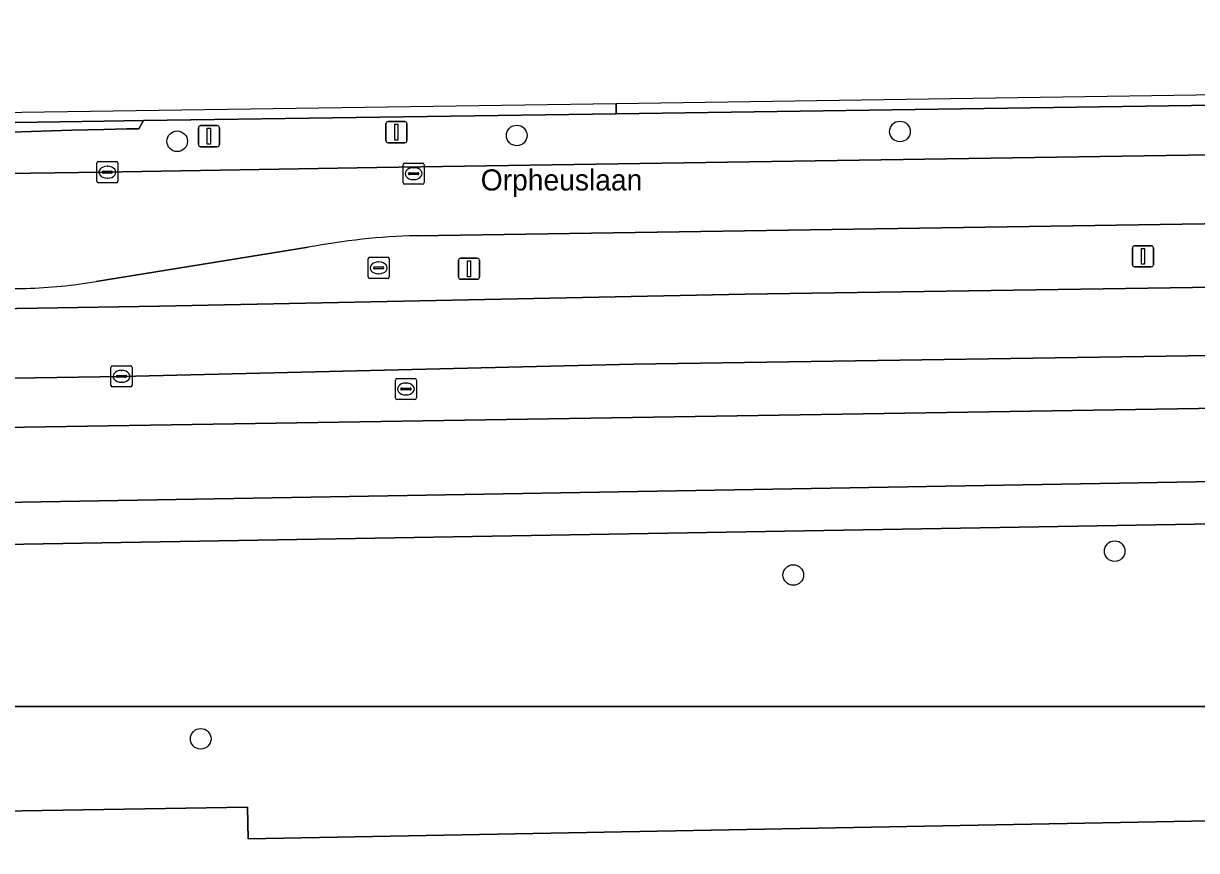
# Model space of a CAD drawing. Extents: x 161758 to 162722, y 384793 to 385405.
# Drawn here: x 162200.5 to 162256.1, y 385350.4 to 385389.6 of the extents above; entities that cross this region are included whole.
import ezdxf

# ---------------------------------------------------------------- set-up
doc = ezdxf.new("R2010")
doc.units = 0
for name, color, linetype in [('IMGEO_Berm_groen', 7, 'Continuous'), ('IMGEO_Boom', 7, 'Continuous'), ('IMGEO_Fietspad_gesloten', 7, 'Continuous'), ('IMGEO_Greppel_droge_sloot', 7, 'Continuous'), ('IMGEO_Groenvoorziening', 7, 'Continuous'), ('IMGEO_Hek', 7, 'Continuous'), ('IMGEO_Kolk', 7, 'Continuous'), ('IMGEO_Lichtmast', 7, 'Continuous'), ('IMGEO_Openbare_ruimte_label', 7, 'Continuous'), ('IMGEO_Rijbaan_lokaal_gesloten', 7, 'Continuous'), ('IMGEO_Rijbaan_lokaal_open', 7, 'Continuous'), ('IMGEO_Rioolput', 7, 'Continuous'), ('IMGEO_Verkeersbordpaal', 7, 'Continuous'), ('IMGEO_Voetpad_open', 7, 'Continuous')]:
    doc.layers.add(name, color=color, linetype=linetype)

msp = doc.modelspace()

# ---------------------------------------------------------------- linework, layer by layer
at = {"layer": 'IMGEO_Berm_groen'}
for points in [[(162448.206, 385387.415), (162445.243, 385388.157), (162443.232, 385388.399), (162423.379, 385388.189), (162414.607, 385388.138), (162283.634, 385386.126), (162263.488, 385385.822), (162228.595, 385385.317), (162206.198, 385385.003), (162205.968, 385384.605), (162205.396, 385384.605), (162204.311, 385384.582), (162202.798, 385384.551), (162199.912, 385384.449), (162195.254, 385384.428), (162192.04, 385384.388), (162191.677, 385384.787), (162189.594, 385384.756), (162154.105, 385384.195)], [(162153.641, 385381.789), (162191.763, 385382.388), (162204.253, 385382.553), (162217.246, 385382.783), (162312.827, 385384.23), (162410.768, 385385.625), (162434.016, 385385.96), (162448.099, 385386.389)], [(162403.86, 385374.889), (162402.9, 385374.878), (162402.901, 385376.061), (162229.409, 385373.457), (162205.151, 385372.883), (162158.028, 385372.147), (162153.757, 385371.662), (162153.722, 385371.658)], [(162192.137, 385370.17), (162199.552, 385370.454), (162335.66, 385372.624)], [(162334.969, 385369.062), (162262.45, 385367.992), (162199.528, 385366.908), (162192.263, 385366.577)], [(162154.507, 385360.425), (162151.789, 385360.357), (162150.992, 385358.051), (162159.583, 385359.12), (162165.376, 385360.213), (162170.222, 385360.838), (162177.201, 385361.095), (162182.531, 385363.894), (162186.248, 385363.968), (162192.408, 385364.581), (162199.591, 385364.909), (162262.482, 385365.992), (162334.984, 385367.062), (162355.205, 385367.058), (162375.991, 385366.088), (162383.594, 385365.585), (162400.648, 385364.015), (162400.746, 385366.014), (162383.752, 385367.579), (162376.104, 385368.085)]]:
    msp.add_lwpolyline(points, dxfattribs=at)
at = {"layer": 'IMGEO_Boom'}
for centre in [(162207.789, 385384.021), (162223.88, 385384.298), (162242.036, 385384.488), (162252.213, 385364.601), (162236.985, 385363.469), (162208.902, 385355.708)]:
    msp.add_circle(centre, 0.489, dxfattribs=at)
at = {"layer": 'IMGEO_Fietspad_gesloten'}
for points in [[(162335.66, 385372.624), (162199.552, 385370.454), (162192.137, 385370.17)], [(162192.263, 385366.577), (162199.528, 385366.908), (162262.45, 385367.992), (162334.969, 385369.062)]]:
    msp.add_lwpolyline(points, dxfattribs=at)
at = {"layer": 'IMGEO_Greppel_droge_sloot'}
for points in [[(162153.729, 385375.343), (162153.782, 385375.344), (162206.944, 385376.203), (162234.699, 385376.782), (162403.236, 385379.286), (162426.371, 385379.655), (162426.501, 385379.723), (162432.165, 385379.785), (162432.018, 385382.777)], [(162432.018, 385382.777), (162411.112, 385382.403), (162393.993, 385382.082), (162339.389, 385381.368), (162219.127, 385379.546)], [(162214.002, 385378.999), (162203.942, 385377.381)], [(162200.627, 385377.052), (162153.77, 385376.293)]]:
    msp.add_lwpolyline(points, dxfattribs=at)
for centre, radius, start, end in [((162219.818, 385348.786), 30.768, 91.2877, 100.8968), ((162199.995, 385400.289), 23.245, 271.5588, 279.7768)]:
    msp.add_arc(centre, radius, start, end, dxfattribs=at)
at = {"layer": 'IMGEO_Groenvoorziening'}
msp.add_lwpolyline([(162400.648, 385364.015), (162383.594, 385365.585), (162375.991, 385366.088), (162355.205, 385367.058), (162334.984, 385367.062), (162262.482, 385365.992), (162199.591, 385364.909), (162192.408, 385364.581), (162186.248, 385363.968), (162185.022, 385359.083), (162186.31, 385357.233), (162276.605, 385357.233), (162354.415, 385358.921), (162400.44, 385359.797)], close=True, dxfattribs=at)
for points in [[(162147.884, 385351.44), (162211.124, 385352.462), (162211.155, 385350.962), (162286.233, 385352.376), (162376.31, 385353.749), (162399.858, 385354.488), (162400.23, 385354.495), (162400.312, 385357.19), (162400.44, 385359.797)], [(162400.44, 385359.797), (162354.415, 385358.921), (162276.605, 385357.233), (162186.31, 385357.233), (162185.022, 385359.083), (162181.43, 385358.098), (162168.743, 385357.936), (162164.05, 385357.113), (162158.836, 385356.939), (162154.408, 385356.121), (162150.398, 385356.327), (162149.796, 385354.342), (162148.453, 385354.749), (162148.371, 385354.456)], [(162385.453, 385347.799), (162399.546, 385348.186), (162399.858, 385354.488), (162376.31, 385353.749), (162286.233, 385352.376), (162211.155, 385350.962), (162211.124, 385352.462), (162147.884, 385351.44)]]:
    msp.add_lwpolyline(points, dxfattribs=at)
at = {"layer": 'IMGEO_Hek'}
msp.add_lwpolyline([(162147.884, 385351.44), (162211.124, 385352.462), (162211.155, 385350.962), (162286.233, 385352.376), (162376.31, 385353.749), (162399.858, 385354.488)], dxfattribs=at)
at = {"layer": 'IMGEO_Kolk'}
for p, q in [((162203.98, 385382.131), (162203.98, 385382.983)), ((162204.055, 385383.057), (162204.907, 385383.057)), ((162204.468, 385382.837), (162204.493, 385382.837)), ((162204.981, 385382.983), (162204.981, 385382.131)), ((162204.239, 385382.551), (162204.239, 385382.563)), ((162204.677, 385382.514), (162204.279, 385382.514)), ((162204.282, 385382.6), (162204.68, 385382.6)), ((162204.491, 385382.277), (162204.466, 385382.277)), ((162204.723, 385382.563), (162204.723, 385382.551)), ((162204.907, 385382.057), (162204.055, 385382.057)), ((162204.725, 385373.383), (162205.577, 385373.383)), ((162204.65, 385372.457), (162204.65, 385373.309)), ((162204.909, 385372.877), (162204.909, 385372.889)), ((162205.347, 385372.84), (162204.949, 385372.84)), ((162204.952, 385372.926), (162205.35, 385372.926)), ((162205.138, 385373.163), (162205.163, 385373.163)), ((162205.393, 385372.889), (162205.393, 385372.877)), ((162205.651, 385373.309), (162205.651, 385372.457)), ((162205.577, 385372.383), (162204.725, 385372.383)), ((162205.161, 385372.603), (162205.136, 385372.603))]:
    msp.add_line(p, q, dxfattribs=at)
for points in [[(162203.98, 385382.131), (162203.98, 385382.983)], [(162204.055, 385383.057), (162204.907, 385383.057)], [(162204.981, 385382.983), (162204.981, 385382.131)], [(162204.907, 385382.057), (162204.055, 385382.057)], [(162204.725, 385373.383), (162205.577, 385373.383)], [(162204.65, 385372.457), (162204.65, 385373.309)], [(162205.651, 385373.309), (162205.651, 385372.457)], [(162205.577, 385372.383), (162204.725, 385372.383)]]:
    msp.add_lwpolyline(points, dxfattribs=at)
for centre, radius, start, end in [((162204.057, 385382.981), 0.0765, 91.552, 178.448), ((162204.057, 385382.981), 0.0765, 91.552, 178.448), ((162204.905, 385382.981), 0.0765, 1.552, 88.448), ((162204.905, 385382.981), 0.0765, 1.552, 88.448), ((162204.279, 385382.56), 0.0403, 85.8775, 175.7526), ((162204.276, 385382.55), 0.0366, 178.938, 274.7102), ((162204.68, 385382.557), 0.043, 264.8664, 352.4533), ((162204.684, 385382.562), 0.0386, 1.7309, 96.639), ((162204.057, 385382.133), 0.0765, 181.552, 268.448), ((162204.057, 385382.133), 0.0765, 181.552, 268.448), ((162204.905, 385382.133), 0.0765, 271.552, 358.448), ((162204.905, 385382.133), 0.0765, 271.552, 358.448), ((162204.727, 385373.307), 0.0765, 91.552, 178.448), ((162204.727, 385373.307), 0.0765, 91.552, 178.448), ((162205.575, 385373.307), 0.0765, 1.552, 88.448), ((162205.575, 385373.307), 0.0765, 1.552, 88.448), ((162204.949, 385372.886), 0.0403, 85.8775, 175.7526), ((162204.946, 385372.876), 0.0366, 178.938, 274.7102), ((162205.35, 385372.883), 0.043, 264.8664, 352.4533), ((162205.354, 385372.888), 0.0386, 1.7309, 96.639), ((162204.727, 385372.459), 0.0765, 181.552, 268.448), ((162204.727, 385372.459), 0.0765, 181.552, 268.448), ((162205.575, 385372.459), 0.0765, 271.552, 358.448), ((162205.575, 385372.459), 0.0765, 271.552, 358.448)]:
    msp.add_arc(centre, radius, start, end, dxfattribs=at)
for centre, major_axis, ratio, start_param, end_param in [((162204.467, 385382.557), (-0.387, 0.002), 0.722429, 4.712389, 7.853982), ((162204.492, 385382.557), (-0.39, 0.002), 0.717154, 1.570796, 4.712389), ((162205.137, 385372.883), (-0.387, 0.002), 0.722429, 4.712389, 7.853982), ((162205.162, 385372.883), (-0.39, 0.002), 0.717154, 1.570796, 4.712389)]:
    msp.add_ellipse(centre, major_axis=major_axis, ratio=ratio, start_param=start_param, end_param=end_param, dxfattribs=at)
at = {"layer": 'IMGEO_Lichtmast'}
for p, q in [((162253.057, 385378.173), (162253.057, 385378.973)), ((162253.057, 385378.973), (162253.057, 385378.173)), ((162253.157, 385379.073), (162253.947, 385379.073)), ((162253.947, 385379.073), (162253.157, 385379.073)), ((162254.047, 385378.973), (162254.047, 385378.173)), ((162254.047, 385378.173), (162254.047, 385378.973)), ((162221.12, 385377.581), (162221.12, 385378.381)), ((162221.12, 385378.381), (162221.12, 385377.581)), ((162221.22, 385378.481), (162222.01, 385378.481)), ((162222.01, 385378.481), (162221.22, 385378.481)), ((162222.11, 385378.381), (162222.11, 385377.581)), ((162222.11, 385377.581), (162222.11, 385378.381)), ((162253.947, 385378.073), (162253.157, 385378.073)), ((162253.157, 385378.073), (162253.947, 385378.073)), ((162222.01, 385377.481), (162221.22, 385377.481)), ((162221.22, 385377.481), (162222.01, 385377.481))]:
    msp.add_line(p, q, dxfattribs=at)
for points in [[(162253.477, 385378.948), (162253.627, 385378.948), (162253.627, 385378.198), (162253.477, 385378.198), (162253.477, 385378.948)], [(162221.54, 385378.356), (162221.69, 385378.356), (162221.69, 385377.606), (162221.54, 385377.606), (162221.54, 385378.356)]]:
    msp.add_lwpolyline(points, dxfattribs=at)
for centre, start, end in [((162253.157, 385378.973), 90, 180), ((162253.157, 385378.973), 90, 180), ((162253.947, 385378.973), 0, 90), ((162253.947, 385378.973), 360, 90), ((162221.22, 385378.381), 90, 180), ((162221.22, 385378.381), 90, 180), ((162222.01, 385378.381), 0, 90), ((162222.01, 385378.381), 360, 90), ((162253.157, 385378.173), 180, 270), ((162253.157, 385378.173), 180, 270), ((162253.947, 385378.173), 270, 0), ((162253.947, 385378.173), 270, 0), ((162221.22, 385377.581), 180, 270), ((162221.22, 385377.581), 180, 270), ((162222.01, 385377.581), 270, 0), ((162222.01, 385377.581), 270, 0)]:
    msp.add_arc(centre, 0.1, start, end, dxfattribs=at)
at = {"layer": 'IMGEO_Rijbaan_lokaal_gesloten'}
for points in [[(162219.127, 385379.546), (162339.389, 385381.368), (162393.993, 385382.082), (162411.112, 385382.403), (162432.018, 385382.777), (162437.689, 385382.879), (162443.578, 385382.984), (162456.299, 385383.459), (162483.099, 385384.709), (162488.117, 385384.861), (162491.004, 385384.944), (162491.978, 385389.606)], [(162457.882, 385387.134), (162448.099, 385386.389), (162434.016, 385385.96), (162410.768, 385385.625), (162312.827, 385384.23), (162217.246, 385382.783), (162204.253, 385382.553), (162191.763, 385382.388), (162153.641, 385381.789), (162153.77, 385376.293), (162200.627, 385377.052)], [(162491.195, 385381.916), (162488.237, 385381.771), (162483.337, 385381.495), (162461.943, 385380.497), (162452.111, 385380.143), (162439.426, 385379.864), (162437.75, 385379.846), (162432.165, 385379.785), (162426.501, 385379.723), (162426.371, 385379.655), (162403.236, 385379.286), (162234.699, 385376.782), (162206.944, 385376.203), (162153.782, 385375.344), (162153.722, 385371.658), (162153.757, 385371.662), (162158.028, 385372.147), (162205.151, 385372.883), (162229.409, 385373.457), (162402.901, 385376.061), (162419.657, 385376.285), (162427.975, 385376.401), (162443.705, 385376.666), (162464.489, 385377.035)], [(162203.942, 385377.381), (162214.002, 385378.999)]]:
    msp.add_lwpolyline(points, dxfattribs=at)
for centre, radius, start, end in [((162219.818, 385348.786), 30.768, 91.2877, 100.8968), ((162199.995, 385400.289), 23.245, 271.5588, 279.7768)]:
    msp.add_arc(centre, radius, start, end, dxfattribs=at)
at = {"layer": 'IMGEO_Rijbaan_lokaal_open'}
msp.add_lwpolyline([(162263.481, 385386.324), (162228.585, 385385.805), (162228.595, 385385.317), (162263.488, 385385.822)], close=True, dxfattribs=at)
msp.add_lwpolyline([(162228.585, 385385.805), (162189.582, 385385.225), (162189.594, 385384.756), (162191.677, 385384.787), (162204.322, 385384.977), (162206.198, 385385.003), (162228.595, 385385.317), (162228.585, 385385.805)], dxfattribs=at)
at = {"layer": 'IMGEO_Rioolput'}
for p, q in [((162218.493, 385382.062), (162218.493, 385382.914)), ((162218.568, 385382.988), (162219.42, 385382.988)), ((162219.494, 385382.914), (162219.494, 385382.062)), ((162218.752, 385382.482), (162218.752, 385382.494)), ((162219.19, 385382.445), (162218.792, 385382.445)), ((162218.795, 385382.531), (162219.193, 385382.531)), ((162218.981, 385382.768), (162219.006, 385382.768)), ((162219.236, 385382.494), (162219.236, 385382.482)), ((162219.42, 385381.988), (162218.568, 385381.988)), ((162219.004, 385382.208), (162218.979, 385382.208)), ((162216.836, 385377.598), (162216.836, 385378.45)), ((162216.911, 385378.524), (162217.763, 385378.524)), ((162217.837, 385378.45), (162217.837, 385377.598)), ((162217.095, 385378.018), (162217.095, 385378.03)), ((162217.533, 385377.981), (162217.135, 385377.981)), ((162217.138, 385378.067), (162217.536, 385378.067)), ((162217.324, 385378.304), (162217.349, 385378.304)), ((162217.579, 385378.03), (162217.579, 385378.018)), ((162217.763, 385377.524), (162216.911, 385377.524)), ((162217.347, 385377.744), (162217.322, 385377.744)), ((162218.201, 385372.784), (162219.053, 385372.784)), ((162218.126, 385371.858), (162218.126, 385372.71)), ((162218.385, 385372.278), (162218.385, 385372.29)), ((162218.823, 385372.241), (162218.425, 385372.241)), ((162218.428, 385372.327), (162218.826, 385372.327)), ((162218.614, 385372.564), (162218.639, 385372.564)), ((162218.869, 385372.29), (162218.869, 385372.278)), ((162219.127, 385372.71), (162219.127, 385371.858)), ((162219.053, 385371.784), (162218.201, 385371.784)), ((162218.637, 385372.004), (162218.612, 385372.004))]:
    msp.add_line(p, q, dxfattribs=at)
for points in [[(162218.493, 385382.062), (162218.493, 385382.914)], [(162218.568, 385382.988), (162219.42, 385382.988)], [(162219.494, 385382.914), (162219.494, 385382.062)], [(162219.42, 385381.988), (162218.568, 385381.988)], [(162216.836, 385377.598), (162216.836, 385378.45)], [(162216.911, 385378.524), (162217.763, 385378.524)], [(162217.837, 385378.45), (162217.837, 385377.598)], [(162217.763, 385377.524), (162216.911, 385377.524)], [(162218.201, 385372.784), (162219.053, 385372.784)], [(162218.126, 385371.858), (162218.126, 385372.71)], [(162219.127, 385372.71), (162219.127, 385371.858)], [(162219.053, 385371.784), (162218.201, 385371.784)]]:
    msp.add_lwpolyline(points, dxfattribs=at)
for centre, radius, start, end in [((162218.57, 385382.912), 0.0765, 91.552, 178.448), ((162218.57, 385382.912), 0.0765, 91.552, 178.448), ((162219.418, 385382.912), 0.0765, 1.552, 88.448), ((162219.418, 385382.912), 0.0765, 1.552, 88.448), ((162218.792, 385382.491), 0.0403, 85.8775, 175.7526), ((162218.789, 385382.481), 0.0366, 178.938, 274.7102), ((162219.193, 385382.488), 0.043, 264.8664, 352.4533), ((162219.197, 385382.493), 0.0386, 1.7309, 96.639), ((162218.57, 385382.064), 0.0765, 181.552, 268.448), ((162218.57, 385382.064), 0.0765, 181.552, 268.448), ((162219.418, 385382.064), 0.0765, 271.552, 358.448), ((162219.418, 385382.064), 0.0765, 271.552, 358.448), ((162216.913, 385378.448), 0.0765, 91.552, 178.448), ((162216.913, 385378.448), 0.0765, 91.552, 178.448), ((162217.761, 385378.448), 0.0765, 1.552, 88.448), ((162217.761, 385378.448), 0.0765, 1.552, 88.448), ((162217.135, 385378.027), 0.0403, 85.8775, 175.7526), ((162217.132, 385378.017), 0.0366, 178.938, 274.7102), ((162217.536, 385378.024), 0.043, 264.8664, 352.4533), ((162217.54, 385378.029), 0.0386, 1.7309, 96.639), ((162216.913, 385377.6), 0.0765, 181.552, 268.448), ((162216.913, 385377.6), 0.0765, 181.552, 268.448), ((162217.761, 385377.6), 0.0765, 271.552, 358.448), ((162217.761, 385377.6), 0.0765, 271.552, 358.448), ((162218.203, 385372.708), 0.0765, 91.552, 178.448), ((162218.203, 385372.708), 0.0765, 91.552, 178.448), ((162219.051, 385372.708), 0.0765, 1.552, 88.448), ((162219.051, 385372.708), 0.0765, 1.552, 88.448), ((162218.425, 385372.287), 0.0403, 85.8775, 175.7526), ((162218.422, 385372.277), 0.0366, 178.938, 274.7102), ((162218.826, 385372.284), 0.043, 264.8664, 352.4533), ((162218.83, 385372.289), 0.0386, 1.7309, 96.639), ((162218.203, 385371.86), 0.0765, 181.552, 268.448), ((162218.203, 385371.86), 0.0765, 181.552, 268.448), ((162219.051, 385371.86), 0.0765, 271.552, 358.448), ((162219.051, 385371.86), 0.0765, 271.552, 358.448)]:
    msp.add_arc(centre, radius, start, end, dxfattribs=at)
for centre, major_axis, ratio, start_param, end_param in [((162218.98, 385382.488), (-0.387, 0.002), 0.722429, 4.712389, 7.853982), ((162219.005, 385382.488), (-0.39, 0.002), 0.717154, 1.570796, 4.712389), ((162217.323, 385378.024), (-0.387, 0.002), 0.722429, 4.712389, 7.853982), ((162217.348, 385378.024), (-0.39, 0.002), 0.717154, 1.570796, 4.712389), ((162218.613, 385372.284), (-0.387, 0.002), 0.722429, 4.712389, 7.853982), ((162218.638, 385372.284), (-0.39, 0.002), 0.717154, 1.570796, 4.712389)]:
    msp.add_ellipse(centre, major_axis=major_axis, ratio=ratio, start_param=start_param, end_param=end_param, dxfattribs=at)
at = {"layer": 'IMGEO_Verkeersbordpaal'}
for p, q in [((162208.796, 385383.866), (162208.796, 385384.666)), ((162208.796, 385384.666), (162208.796, 385383.866)), ((162208.896, 385384.766), (162209.686, 385384.766)), ((162209.686, 385384.766), (162208.896, 385384.766)), ((162209.786, 385384.666), (162209.786, 385383.866)), ((162209.786, 385383.866), (162209.786, 385384.666)), ((162217.681, 385384.055), (162217.681, 385384.855)), ((162217.681, 385384.855), (162217.681, 385384.055)), ((162217.781, 385384.955), (162218.571, 385384.955)), ((162218.571, 385384.955), (162217.781, 385384.955)), ((162218.671, 385384.855), (162218.671, 385384.055)), ((162218.671, 385384.055), (162218.671, 385384.855)), ((162218.571, 385383.955), (162217.781, 385383.955)), ((162217.781, 385383.955), (162218.571, 385383.955)), ((162209.686, 385383.766), (162208.896, 385383.766)), ((162208.896, 385383.766), (162209.686, 385383.766))]:
    msp.add_line(p, q, dxfattribs=at)
for points in [[(162209.216, 385384.641), (162209.366, 385384.641), (162209.366, 385383.891), (162209.216, 385383.891), (162209.216, 385384.641)], [(162218.101, 385384.83), (162218.251, 385384.83), (162218.251, 385384.08), (162218.101, 385384.08), (162218.101, 385384.83)]]:
    msp.add_lwpolyline(points, dxfattribs=at)
for centre, start, end in [((162208.896, 385384.666), 90, 180), ((162208.896, 385384.666), 90, 180), ((162209.686, 385384.666), 0, 90), ((162209.686, 385384.666), 360, 90), ((162217.781, 385384.855), 90, 180), ((162217.781, 385384.855), 90, 180), ((162218.571, 385384.855), 0, 90), ((162218.571, 385384.855), 360, 90), ((162217.781, 385384.055), 180, 270), ((162217.781, 385384.055), 180, 270), ((162218.571, 385384.055), 270, 0), ((162218.571, 385384.055), 270, 0), ((162208.896, 385383.866), 180, 270), ((162208.896, 385383.866), 180, 270), ((162209.686, 385383.866), 270, 0), ((162209.686, 385383.866), 270, 0)]:
    msp.add_arc(centre, 0.1, start, end, dxfattribs=at)
at = {"layer": 'IMGEO_Voetpad_open'}
msp.add_lwpolyline([(162206.198, 385385.003), (162204.322, 385384.977), (162191.677, 385384.787), (162192.04, 385384.388), (162195.254, 385384.428), (162199.912, 385384.449), (162202.798, 385384.551), (162204.311, 385384.582), (162205.396, 385384.605), (162205.968, 385384.605)], close=True, dxfattribs=at)

# ---------------------------------------------------------------- texts
at = {"layer": 'IMGEO_Openbare_ruimte_label'}
msp.add_text('Orpheuslaan', height=1, dxfattribs=at).set_placement((162222.173, 385381.691))

doc.saveas('drawing.dxf')
